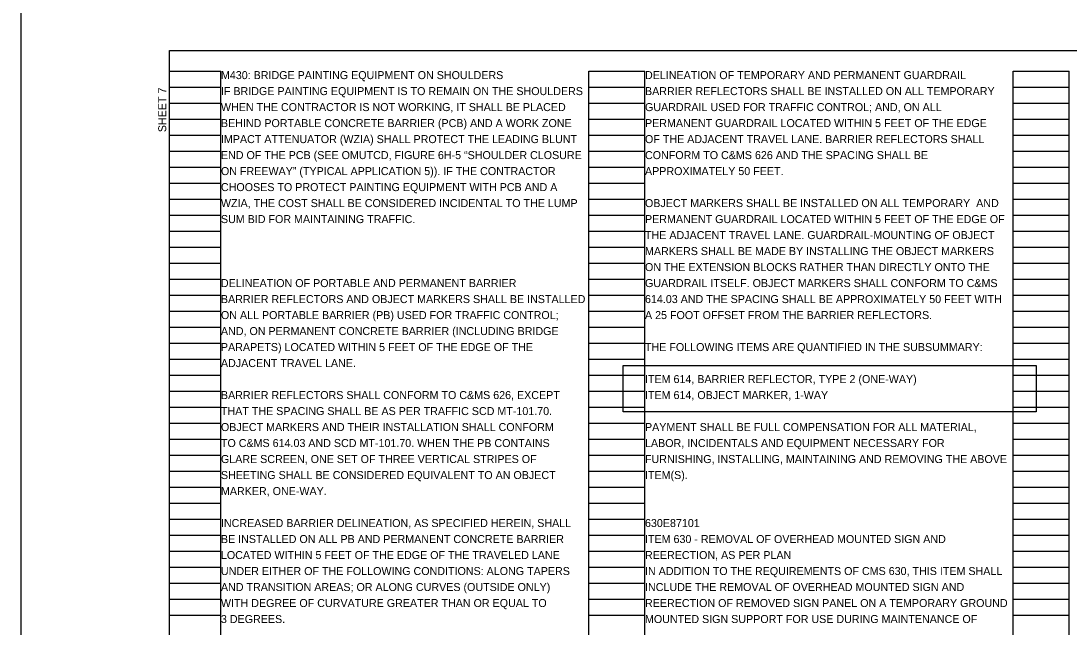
# Model space of a CAD drawing. Extents: x 1820207 to 1820557, y 740216 to 740315.
# Drawn here: x 1820438.01 to 1820456.35, y 740265.65 to 740276.26 of the extents above; entities that cross this region are included whole.
import ezdxf

# ---------------------------------------------------------------- set-up
doc = ezdxf.new("R2010")
doc.units = 0
for name, color, linetype in [('SC_Scratch1', 7, 'Continuous'), ('SC_Scratch2', 7, 'Continuous'), ('SC_Scratch4', 7, 'Continuous'), ('SC_Shading1', 7, 'Continuous'), ('SH_Text', 7, 'Continuous')]:
    doc.layers.add(name, color=color, linetype=linetype)

msp = doc.modelspace()

# ---------------------------------------------------------------- linework, layer by layer
at = {"layer": 'SC_Scratch1'}
for p, q in [((1820440.608, 740255.222), (1820440.608, 740275.382)), ((1820440.608, 740275.382), (1820441.508, 740275.382)), ((1820441.508, 740255.222), (1820441.508, 740275.382)), ((1820447.948, 740255.222), (1820447.948, 740275.382)), ((1820447.948, 740275.382), (1820448.928, 740275.382)), ((1820448.928, 740255.222), (1820448.928, 740275.382)), ((1820455.368, 740255.222), (1820455.368, 740275.382)), ((1820455.368, 740275.382), (1820456.348, 740275.382)), ((1820456.348, 740255.222), (1820456.348, 740275.382)), ((1820440.608, 740275.102), (1820441.508, 740275.102)), ((1820447.948, 740275.102), (1820448.928, 740275.102)), ((1820455.368, 740275.102), (1820456.348, 740275.102)), ((1820440.608, 740274.822), (1820441.508, 740274.822)), ((1820447.948, 740274.822), (1820448.928, 740274.822)), ((1820455.368, 740274.822), (1820456.348, 740274.822)), ((1820440.608, 740274.542), (1820441.508, 740274.542)), ((1820447.948, 740274.542), (1820448.928, 740274.542)), ((1820455.368, 740274.542), (1820456.348, 740274.542)), ((1820440.608, 740274.262), (1820441.508, 740274.262)), ((1820447.948, 740274.262), (1820448.928, 740274.262)), ((1820455.368, 740274.262), (1820456.348, 740274.262)), ((1820440.608, 740273.982), (1820441.508, 740273.982)), ((1820447.948, 740273.982), (1820448.928, 740273.982)), ((1820455.368, 740273.982), (1820456.348, 740273.982)), ((1820440.608, 740273.702), (1820441.508, 740273.702)), ((1820447.948, 740273.702), (1820448.928, 740273.702)), ((1820455.368, 740273.702), (1820456.348, 740273.702)), ((1820440.608, 740273.422), (1820441.508, 740273.422)), ((1820447.948, 740273.422), (1820448.928, 740273.422)), ((1820455.368, 740273.422), (1820456.348, 740273.422)), ((1820440.608, 740273.142), (1820441.508, 740273.142)), ((1820447.948, 740273.142), (1820448.928, 740273.142)), ((1820455.368, 740273.142), (1820456.348, 740273.142)), ((1820440.608, 740272.862), (1820441.508, 740272.862)), ((1820447.948, 740272.862), (1820448.928, 740272.862)), ((1820455.368, 740272.862), (1820456.348, 740272.862)), ((1820440.608, 740272.582), (1820441.508, 740272.582)), ((1820447.948, 740272.582), (1820448.928, 740272.582)), ((1820455.368, 740272.582), (1820456.348, 740272.582)), ((1820440.608, 740272.302), (1820441.508, 740272.302)), ((1820447.948, 740272.302), (1820448.928, 740272.302)), ((1820455.368, 740272.302), (1820456.348, 740272.302)), ((1820440.608, 740272.022), (1820441.508, 740272.022)), ((1820447.948, 740272.022), (1820448.928, 740272.022)), ((1820455.368, 740272.022), (1820456.348, 740272.022)), ((1820440.608, 740271.742), (1820441.508, 740271.742)), ((1820447.948, 740271.742), (1820448.928, 740271.742)), ((1820455.368, 740271.742), (1820456.348, 740271.742)), ((1820440.608, 740271.462), (1820441.508, 740271.462)), ((1820447.948, 740271.462), (1820448.928, 740271.462)), ((1820455.368, 740271.462), (1820456.348, 740271.462)), ((1820440.608, 740271.182), (1820441.508, 740271.182)), ((1820447.948, 740271.182), (1820448.928, 740271.182)), ((1820455.368, 740271.182), (1820456.348, 740271.182)), ((1820440.608, 740270.902), (1820441.508, 740270.902)), ((1820447.948, 740270.902), (1820448.928, 740270.902)), ((1820455.368, 740270.902), (1820456.348, 740270.902)), ((1820440.608, 740270.622), (1820441.508, 740270.622)), ((1820447.948, 740270.622), (1820448.928, 740270.622)), ((1820455.368, 740270.622), (1820456.348, 740270.622)), ((1820440.608, 740270.342), (1820441.508, 740270.342)), ((1820447.948, 740270.342), (1820448.928, 740270.342)), ((1820455.368, 740270.342), (1820456.348, 740270.342)), ((1820440.608, 740270.062), (1820441.508, 740270.062)), ((1820447.948, 740270.062), (1820448.928, 740270.062)), ((1820455.368, 740270.062), (1820456.348, 740270.062)), ((1820440.608, 740269.782), (1820441.508, 740269.782)), ((1820447.948, 740269.782), (1820448.928, 740269.782)), ((1820455.368, 740269.782), (1820456.348, 740269.782)), ((1820440.608, 740269.502), (1820441.508, 740269.502)), ((1820447.948, 740269.502), (1820448.928, 740269.502)), ((1820455.368, 740269.502), (1820456.348, 740269.502)), ((1820440.608, 740269.222), (1820441.508, 740269.222)), ((1820447.948, 740269.222), (1820448.928, 740269.222)), ((1820455.368, 740269.222), (1820456.348, 740269.222)), ((1820440.608, 740268.942), (1820441.508, 740268.942)), ((1820447.948, 740268.942), (1820448.928, 740268.942)), ((1820455.368, 740268.942), (1820456.348, 740268.942)), ((1820440.608, 740268.662), (1820441.508, 740268.662)), ((1820447.948, 740268.662), (1820448.928, 740268.662)), ((1820455.368, 740268.662), (1820456.348, 740268.662)), ((1820440.608, 740268.382), (1820441.508, 740268.382)), ((1820447.948, 740268.382), (1820448.928, 740268.382)), ((1820455.368, 740268.382), (1820456.348, 740268.382)), ((1820440.608, 740268.102), (1820441.508, 740268.102)), ((1820447.948, 740268.102), (1820448.928, 740268.102)), ((1820455.368, 740268.102), (1820456.348, 740268.102)), ((1820440.608, 740267.822), (1820441.508, 740267.822)), ((1820447.948, 740267.822), (1820448.928, 740267.822)), ((1820455.368, 740267.822), (1820456.348, 740267.822)), ((1820440.608, 740267.542), (1820441.508, 740267.542)), ((1820447.948, 740267.542), (1820448.928, 740267.542)), ((1820455.368, 740267.542), (1820456.348, 740267.542)), ((1820440.608, 740267.262), (1820441.508, 740267.262)), ((1820447.948, 740267.262), (1820448.928, 740267.262)), ((1820455.368, 740267.262), (1820456.348, 740267.262)), ((1820440.608, 740266.982), (1820441.508, 740266.982)), ((1820447.948, 740266.982), (1820448.928, 740266.982)), ((1820455.368, 740266.982), (1820456.348, 740266.982)), ((1820440.608, 740266.702), (1820441.508, 740266.702)), ((1820447.948, 740266.702), (1820448.928, 740266.702)), ((1820455.368, 740266.702), (1820456.348, 740266.702)), ((1820440.608, 740266.422), (1820441.508, 740266.422)), ((1820447.948, 740266.422), (1820448.928, 740266.422)), ((1820455.368, 740266.422), (1820456.348, 740266.422)), ((1820440.608, 740266.142), (1820441.508, 740266.142)), ((1820447.948, 740266.142), (1820448.928, 740266.142)), ((1820455.368, 740266.142), (1820456.348, 740266.142)), ((1820440.608, 740265.862), (1820441.508, 740265.862)), ((1820447.948, 740265.862), (1820448.928, 740265.862)), ((1820455.368, 740265.862), (1820456.348, 740265.862))]:
    msp.add_line(p, q, dxfattribs=at)
at = {"layer": 'SC_Scratch2'}
msp.add_lwpolyline([(1820440.608, 740275.742), (1820471.108, 740275.742), (1820471.108, 740254.742), (1820440.608, 740254.742)], close=True, dxfattribs=at)
at = {"layer": 'SC_Shading1'}
for points in [[(1820438.009, 740251.753), (1820473.843, 740251.753), (1820473.843, 740281.035), (1820438.009, 740281.035)], [(1820448.548, 740270.23), (1820455.771, 740270.23), (1820455.771, 740269.421), (1820448.548, 740269.421)]]:
    msp.add_lwpolyline(points, close=True, dxfattribs=at)

# ---------------------------------------------------------------- texts
at = {"layer": 'SC_Scratch4'}
msp.add_text('630E87101', height=0.14, dxfattribs=at).set_placement((1820448.928, 740267.402))
at = {"layer": 'SH_Text'}
for s, p in [('M430: BRIDGE PAINTING EQUIPMENT ON SHOULDERS', (1820441.508, 740275.242)), ('DELINEATION OF TEMPORARY AND PERMANENT GUARDRAIL', (1820448.928, 740275.242)), ('IF BRIDGE PAINTING EQUIPMENT IS TO REMAIN ON THE SHOULDERS ', (1820441.508, 740274.962)), ('BARRIER REFLECTORS SHALL BE INSTALLED ON ALL TEMPORARY ', (1820448.928, 740274.962)), ('WHEN THE CONTRACTOR IS NOT WORKING, IT SHALL BE PLACED ', (1820441.508, 740274.682)), ('GUARDRAIL USED FOR TRAFFIC CONTROL; AND, ON ALL ', (1820448.928, 740274.682)), ('BEHIND PORTABLE CONCRETE BARRIER (PCB) AND A WORK ZONE ', (1820441.508, 740274.402)), ('PERMANENT GUARDRAIL LOCATED WITHIN 5 FEET OF THE EDGE ', (1820448.928, 740274.402)), ('IMPACT ATTENUATOR (WZIA) SHALL PROTECT THE LEADING BLUNT ', (1820441.508, 740274.122)), ('OF THE ADJACENT TRAVEL LANE. BARRIER REFLECTORS SHALL ', (1820448.928, 740274.122)), ('END OF THE PCB (SEE OMUTCD, FIGURE 6H-5 “SHOULDER CLOSURE ', (1820441.508, 740273.842)), ('CONFORM TO C&MS 626 AND THE SPACING SHALL BE ', (1820448.928, 740273.842)), ('ON FREEWAY” (TYPICAL APPLICATION 5)). IF THE CONTRACTOR ', (1820441.508, 740273.562)), ('APPROXIMATELY 50 FEET. ', (1820448.928, 740273.562)), ('CHOOSES TO PROTECT PAINTING EQUIPMENT WITH PCB AND A ', (1820441.508, 740273.282)), ('WZIA, THE COST SHALL BE CONSIDERED INCIDENTAL TO THE LUMP ', (1820441.508, 740273.002)), ('OBJECT MARKERS SHALL BE INSTALLED ON ALL TEMPORARY  AND', (1820448.928, 740273.002)), ('SUM BID FOR MAINTAINING TRAFFIC.', (1820441.508, 740272.722)), ('PERMANENT GUARDRAIL LOCATED WITHIN 5 FEET OF THE EDGE OF', (1820448.928, 740272.722)), ('THE ADJACENT TRAVEL LANE. GUARDRAIL-MOUNTING OF OBJECT ', (1820448.928, 740272.442)), ('MARKERS SHALL BE MADE BY INSTALLING THE OBJECT MARKERS ', (1820448.928, 740272.162)), ('ON THE EXTENSION BLOCKS RATHER THAN DIRECTLY ONTO THE ', (1820448.928, 740271.882)), ('DELINEATION OF PORTABLE AND PERMANENT BARRIER', (1820441.508, 740271.602)), ('GUARDRAIL ITSELF. OBJECT MARKERS SHALL CONFORM TO C&MS ', (1820448.928, 740271.602)), ('BARRIER REFLECTORS AND OBJECT MARKERS SHALL BE INSTALLED ', (1820441.508, 740271.322)), ('614.03 AND THE SPACING SHALL BE APPROXIMATELY 50 FEET WITH ', (1820448.928, 740271.322)), ('ON ALL PORTABLE BARRIER (PB) USED FOR TRAFFIC CONTROL; ', (1820441.508, 740271.042)), ('A 25 FOOT OFFSET FROM THE BARRIER REFLECTORS.', (1820448.928, 740271.042)), ('AND, ON PERMANENT CONCRETE BARRIER (INCLUDING BRIDGE ', (1820441.508, 740270.762)), ('PARAPETS) LOCATED WITHIN 5 FEET OF THE EDGE OF THE ', (1820441.508, 740270.482)), ('THE FOLLOWING ITEMS ARE QUANTIFIED IN THE SUBSUMMARY:', (1820448.928, 740270.482)), ('ADJACENT TRAVEL LANE.', (1820441.508, 740270.202)), ('ITEM 614, BARRIER REFLECTOR, TYPE 2 (ONE-WAY)', (1820448.928, 740269.922)), ('BARRIER REFLECTORS SHALL CONFORM TO C&MS 626, EXCEPT ', (1820441.508, 740269.642)), ('ITEM 614, OBJECT MARKER, 1-WAY', (1820448.928, 740269.642)), ('THAT THE SPACING SHALL BE AS PER TRAFFIC SCD MT-101.70. ', (1820441.508, 740269.362)), ('OBJECT MARKERS AND THEIR INSTALLATION SHALL CONFORM ', (1820441.508, 740269.082)), ('PAYMENT SHALL BE FULL COMPENSATION FOR ALL MATERIAL, ', (1820448.928, 740269.082)), ('TO C&MS 614.03 AND SCD MT-101.70. WHEN THE PB CONTAINS ', (1820441.508, 740268.802)), ('LABOR, INCIDENTALS AND EQUIPMENT NECESSARY FOR ', (1820448.928, 740268.802)), ('GLARE SCREEN, ONE SET OF THREE VERTICAL STRIPES OF ', (1820441.508, 740268.522)), ('FURNISHING, INSTALLING, MAINTAINING AND REMOVING THE ABOVE ', (1820448.928, 740268.522)), ('SHEETING SHALL BE CONSIDERED EQUIVALENT TO AN OBJECT ', (1820441.508, 740268.242)), ('ITEM(S).', (1820448.928, 740268.242)), ('MARKER, ONE-WAY.', (1820441.508, 740267.962)), ('INCREASED BARRIER DELINEATION, AS SPECIFIED HEREIN, SHALL ', (1820441.508, 740267.402)), ('BE INSTALLED ON ALL PB AND PERMANENT CONCRETE BARRIER ', (1820441.508, 740267.122)), ('ITEM 630 - REMOVAL OF OVERHEAD MOUNTED SIGN AND ', (1820448.928, 740267.122)), ('LOCATED WITHIN 5 FEET OF THE EDGE OF THE TRAVELED LANE ', (1820441.508, 740266.842)), ('REERECTION, AS PER PLAN', (1820448.928, 740266.842)), ('UNDER EITHER OF THE FOLLOWING CONDITIONS: ALONG TAPERS ', (1820441.508, 740266.562)), ('IN ADDITION TO THE REQUIREMENTS OF CMS 630, THIS ITEM SHALL ', (1820448.928, 740266.562)), ('AND TRANSITION AREAS; OR ALONG CURVES (OUTSIDE ONLY) ', (1820441.508, 740266.282)), ('INCLUDE THE REMOVAL OF OVERHEAD MOUNTED SIGN AND', (1820448.928, 740266.282)), ('WITH DEGREE OF CURVATURE GREATER THAN OR EQUAL TO ', (1820441.508, 740266.002)), ('REERECTION OF REMOVED SIGN PANEL ON A TEMPORARY GROUND ', (1820448.928, 740266.002)), ('3 DEGREES.', (1820441.508, 740265.722)), ('MOUNTED SIGN SUPPORT FOR USE DURING MAINTENANCE OF', (1820448.928, 740265.722))]:
    msp.add_text(s, height=0.14, dxfattribs=at).set_placement(p)
msp.add_text('SHEET 7', height=0.14, rotation=90, dxfattribs=at).set_placement((1820440.551, 740274.313))

doc.saveas('drawing.dxf')
